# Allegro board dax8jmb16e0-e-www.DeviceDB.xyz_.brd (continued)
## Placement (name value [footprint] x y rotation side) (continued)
PC8101  0.22U/10V_4  [C0402]  13.04 112.78 180 bottom
PC8102  3900p/50V_4  [C0402]  8.14 108.03 270 bottom
PC8103  0.1U/16V_4  [C0402]  6.79 116.54 0 bottom
PC8104  *0.01u/50V_4  [C0402]  10.32 116.54 180 bottom
PC8105  1U/6.3V_4  [C0402]  40.11 79.56 0 top
PC8200  *1u/25V_6  [C0603]  142.27 23.25 270 top
PC8201  0.1U/25V_4  [C0402]  144.79 21.49 0 top
PC8203  0.1U/25V_4  [C0402]  125.61 30.31 0 bottom
PC8204  0.1U/25V_4  [C0402]  123.86 30.31 0 bottom
PC8205  0.1U/25V_4  [C0402]  123.93 31.3 0 bottom
PC8206  2200P/50V_4  [C0402]  116.04 34.09 270 bottom
PC8207  10u/25V_6  [C0603]  115.78 29.7 90 top
PC8208  *10u/25V_6  [C0603]  117.2 30.92 90 top
PC8209  0.1U/25V_4  [C0402]  118.47 30.16 270 top
PC8210  2.2u/16V_6  [C0603]  122.59 22.69 0 top
PC8211  1u/25V_6  [C0603]  123.87 27.06 0 bottom
PC8212  0.047U/25V_4  [C0402]  122.77 25.58 180 bottom
PC8213  *1000p/50V_4  [C0402]  128.61 28.89 270 bottom
PC8214  *68u/25V_7343H2.9  [CC7343-3H]  74.81 32.14 180 bottom
PC8215  0.1U/25V_4  [C0402]  80.55 32.85 270 bottom
PC8216  2200p/50V_4  [C0402]  114.59 27.72 180 top
PC8217  0.1U/25V_4  [C0402]  125.56 18.14 90 bottom
PC8218  0.1U/25V_4  [C0402]  125.61 16.67 180 bottom
PC8219  0.1U/25V_4  [C0402]  126.53 18.14 90 bottom
PC8220  100P/50V_4  [C0402]  130.08 27.41 180 bottom
PC8221  100P/50V_4  [C0402]  131.91 27.79 270 bottom
PC8222  0.1U/16V_4  [C0402]  102.47 33.2 270 bottom
PC8223  *100p/50V_4  [C0402]  134.09 26.17 0 bottom
PC8224  220P/50V_4  [C0402]  131.99 22.33 0 bottom
PC8225  *33u/25V_D6.3H3  [ECAP7X3_5-7_2]  119.21 30.08 90 bottom
PC8226  *10u/25V_6  [C0603]  87.36 32.39 270 bottom
PC8227  10u/25V_6  [C0603]  90.36 32.36 270 bottom
PC8228  10u/25V_6  [C0603]  88.86 32.39 270 bottom
PC8500  3900p/50V_4  [C0402]  156.9 11.64 180 top
PC8501  100p/50V_4  [C0402]  199.37 30.66 270 top
PC8502  0.22u/10V_4  [C0402]  197.26 30.18 270 top
PC8503  *1u/6.3V_4  [C0402]  167.72 11.33 0 top
PC8504  0.1u/25V_4  [C0402]  83.17 28.63 0 top
PC8505  0.1u/25V_4  [C0402]  80.48 30.03 90 bottom
PC8506  2200p/25V_2  [C0201]  82.79 33.2 270 bottom
PC8507  100p/50V_4  [C0402]  90.41 30.03 270 top
PC8508  100p/50V_4  [C0402]  83.8 29.9 180 top
PC8509  *220p/50V_4  [C0402]  171.92 8.87 270 top
PC8600  0.1U/25V_4  [C0402]  180.04 23.14 270 top
PC8601  2.2u/25V_4  [C0402_2]  183.69 21.32 0 bottom
PC8602  2.2u/25V_4  [C0402_2]  181.92 20.71 270 top
PC8603  2.2u/25V_4  [C0402_2]  183.75 22.66 0 bottom
PC8604  *2.2u/25V_4  [C0402_2]  183.69 21.32 0 top
PC8605  0.1U/25V_4  [C0402]  182.23 20.5 270 bottom
PC8606  2200P/50V_4  [C0402]  181.21 20.25 270 bottom
PC8607  *15u/25V_7343H1.2  [CC7343]  184.44 30.59 90 bottom
PC8608  0.1U/25V_4  [C0402]  179.79 25.28 0 bottom
PC8609  *0.1u/6.3V_2  [C0201]  176.23 22.15 270 bottom
PC8610  2200P/50V_4  [C0402]  177.61 22.31 90 top
PC8611  22U/6.3V_6  [C0603]  177.63 32.75 90 top
PC8612  22U/6.3V_6  [C0603]  176.21 32.75 90 top
PC8613  22U/6.3V_6  [C0603]  174.76 32.75 90 top
PC8614  22U/6.3V_6  [C0603]  173.34 32.77 90 top
PC8615  0.1u/6.3V_2  [C0201]  181.21 34.57 0 bottom
PC8616  *150u/6.3V_7343H1.9  [CC7343]  172.65 30.59 270 bottom
PC8617  2.2U/10V_4  [C0402]  177.45 25.3 0 bottom
PC8620  47p/50V_4  [C0402]  175.57 25.35 180 bottom
PC8621  0.1U/25V_4  [C0402]  185.63 23.5 270 top
PC8622  *2.2u/25V_4  [C0402_2]  187.36 20.23 180 bottom
PC8623  *2.2u/25V_4  [C0402_2]  187.25 21.43 180 bottom
PC8624  *2.2u/25V_4  [C0402_2]  187.31 22.28 180 top
PC8625  *2.2u/25V_4  [C0402_2]  187.26 20.74 180 top
PC8626  0.1U/25V_4  [C0402]  187.26 23.69 180 bottom
PC8627  2200P/50V_4  [C0402]  187.26 22.67 180 bottom
PC8628  *15u/25V_7343H1.2  [CC7343]  193.38 27.34 90 top
PC8629  0.1U/25V_4  [C0402]  189.97 18.73 180 bottom
PC8630  *2200p/50V_4  [C0402]  187.31 24.69 0 bottom
PC8631  22U/6.3V_6  [C0603]  194.57 29.75 90 bottom
PC8632  22U/6.3V_6  [C0603]  196.17 33.91 270 bottom
PC8633  22U/6.3V_6  [C0603]  194.65 33.91 270 bottom
PC8634  22U/6.3V_6  [C0603]  195.99 29.75 90 bottom
PC8635  *150u/6.3V_7343H1.9  [CC7343]  201.68 31.04 270 bottom
PC8636  0.1u/6.3V_2  [C0201]  197.34 29.01 90 bottom
PC8637  *0.1u/6.3V_2  [C0201]  194.5 22.67 90 bottom
PC8638  2.2U/10V_4  [C0402]  191.88 19.51 0 bottom
PC8639  10u/6.3V_4  [C0402]  193.58 19.67 270 bottom
PC8641  1000p/25V_4  [C0402]  195.18 20 0 bottom
PC8642  10u/25V_6  [C0603]  188.07 18.29 90 bottom
PC8700  *0.1u/6.3V_2  [C0201]  145.5 13.9 0 bottom
PC8701  *0.1u/6.3V_2  [C0201]  146.24 13.19 0 bottom
PC8702  2200p/25V_2  [C0201]  153.81 25.46 180 bottom
PC8703  0.1u/25V_4  [C0402]  147.13 23.63 90 top
PC8704  0.1u/25V_4  [C0402]  153.41 22.07 180 bottom
PC8705  2.2u/25V_4  [C0402_2]  153.41 23.19 180 bottom
PC8706  *2.2u/25V_4  [C0402_2]  150.97 22.46 90 top
PC8707  *2.2u/25V_4  [C0402_2]  149.78 22.47 90 top
PC8708  2.2u/25V_4  [C0402_2]  153.81 24.47 180 bottom
PC8709  *15u/25V_7343H1.2  [CC7343]  153.25 30.59 90 bottom
PC8710  10u/6.3V_4  [C0402]  149.03 17.79 90 bottom
PC8711  0.1u/25V_4  [C0402]  143.67 19.56 180 bottom
PC8712  0.1u/6.3V_2  [C0201]  149.84 15.04 90 bottom
PC8713  0.033u/16V_4  [C0402]  148.52 15.73 180 bottom
PC8714  *10u/6.3V_4  [C0402]  147.81 19.36 180 bottom
PC8715  1u/6.3V_4  [C0402]  141.08 16.36 180 bottom
PC8716  22u/6.3V_6  [C0603]  142.07 33.84 270 bottom
PC8717  22u/6.3V_6  [C0603]  140.52 27.87 90 bottom
PC8718  *22u/6.3V_6  [C0603]  134.37 29.7 90 bottom
PC8719  *22u/6.3V_6  [C0603]  140.65 33.84 270 bottom
PC8720  *330u/2V_7343H1.9  [CC7343]  137.45 30.59 270 bottom
PC8721  0.1u/6.3V_2  [C0201]  143.21 34.47 90 bottom
PC8722  2200p/25V_2  [C0201]  146.44 22 90 bottom
PC8723  4.7u/6.3V_4  [C0402_2]  162.42 59.57 180 top
PC8724  0.1u/6.3V_2  [C0201]  162.82 60.66 270 top
PC8725  0.22u/6.3V_2  [C0201]  166.91 57.89 180 top
PC8726  22U/6.3V_6  [C0603]  165.74 60.2 90 top
PC8727  *22U/6.3V_6  [C0603]  164.3 60.2 90 top
PC8728  *22p/50V_4  [C0402]  159.98 56.24 270 top
PC8800  4.7u/6.3V_4  [C0402_2]  46.97 98.35 90 top
PC8801  0.1U/16V_4  [C0402]  37.27 93.3 270 top
PC8802  0.1U/16V_4  [C0402]  45.45 93.3 270 top
PC8803  1U/6.3V_4  [C0402]  37.27 95.31 270 top
PC8804  0.01U/50V_4  [C0402]  46.85 103.69 90 top
PC8805  *0.1U/16V_4  [C0402]  47.35 96.65 180 top
PC8806  *0.1U/16V_4  [C0402]  43.26 109.63 90 top
PC8807  *0.1U/16V_4  [C0402]  46.46 95.28 90 top
PC8808  *0.1U/16V_4  [C0402]  36.74 109.2 0 top
PC8809  180p/25V_2  [C0201]  36 98.74 180 top
PC8810  100p/25V_2  [C0201]  36 97.9 180 top
PC8811  22p/25V_2  [C0201]  36 97.06 180 top
PC8812  *0.1U/16V_4  [C0402]  34.48 108.08 270 top
PC8813  *330p/50V_4  [C0402]  46.85 101.91 90 top
PC8814  1U/6.3V_4  [C0402]  46.85 100.13 270 top
PC8815  *680p/50V_4  [C0402]  42.65 105.03 0 top
PC8816  *330p/50V_4  [C0402]  38.59 106.23 180 top
PC8817  330p/50V_4  [C0402]  36.18 103.43 270 top
PC8900  2200P/50V_4  [C0402]  63.92 112.96 0 bottom
PC8901  0.1U/25V_4  [C0402]  63.92 113.98 180 bottom
PC8902  2.2u/25V_4  [C0402_2]  63.86 115.37 180 bottom
PC8903  0.1U/25V_4  [C0402_2]  55.61 119.56 0 top
PC8904  2.2u/25V_4  [C0402_2]  55.61 120.78 0 top
PC8905  2.2u/25V_4  [C0402_2]  65.11 116.88 180 top
PC8906  *15u/25V_7343H1.2  [CC7343]  60.18 123.12 90 bottom
PC8907  0.1U/25V_4  [C0402]  68.81 79.36 0 bottom
PC8908  1U/6.3V_4  [C0402]  54.52 113.8 90 bottom
PC8909  0.1u/25V_4  [C0402]  54.34 107.88 180 bottom
PC8910  330u/2V_7343H1.9  [CC7343]  84.03 120.17 90 bottom
PC8911  *2200p/50V_4  [C0402]  68.44 114.1 90 bottom
PC8912  0.22u/25V_4  [C0402]  51.56 115.34 90 bottom
PC8913  *0.1u/50V_4  [C0402]  51.29 113.98 0 bottom
PC8914  2200P/50V_4  [C0402]  63.02 122.36 90 bottom
PC8915  0.1U/25V_4  [C0402]  65.04 118.98 180 top
PC8916  2.2u/25V_4  [C0402_2]  65.05 120.06 180 top
PC8917  2.2u/25V_4  [C0402_2]  65.05 121.25 180 top
PC8918  2.2u/25V_4  [C0402_2]  65.31 122.36 270 bottom
PC8919  2.2u/25V_4  [C0402_2]  64.11 122.36 270 bottom
PC8920  *15u/25V_7343H1.2  [CC7343]  60.18 112.71 270 bottom
PC8921  1U/6.3V_4  [C0402]  54.42 121.8 90 bottom
PC8922  0.1u/25V_4  [C0402]  54.59 115.63 180 bottom
PC8923  330u/2V_7343H1.9  [CC7343]  88.83 121.54 90 bottom
PC8924  *2200p/50V_4  [C0402]  68.54 117.2 0 top
PC8925  0.22u/25V_4  [C0402]  51.08 121.97 0 bottom
PC8926  *0.1u/50V_4  [C0402]  50.27 120.2 270 bottom
PC8927  *330u/2V_7343H1.9  [CC7343]  93.56 124.95 90 bottom
PC8928  *330u/2V_7343H1.9  [CC7343]  98.28 124.97 90 bottom
PC9000  *2.2u/25V_4  [C0402_2]  57.01 95.18 0 bottom
PC9001  *15u/25V_7343H1.2  [CC7343]  62.84 86.08 180 bottom
PC9002  1U/6.3V_4  [C0402]  54.34 105.47 90 bottom
PC9003  2200P/50V_4  [C0402]  57.01 97.59 180 bottom
PC9004  0.1U/25V_4  [C0402]  57.01 96.45 0 bottom
PC9005  2.2u/25V_4  [C0402_2]  57.03 97.36 0 top
PC9006  2.2u/25V_4  [C0402_2]  57.01 96.17 0 top
PC9007  0.1U/25V_4  [C0402_2]  57.01 94.98 0 top
PC9008  0.1u/25V_4  [C0402]  53.58 98.99 90 bottom
PC9009  330u/2V_7343H1.9  [CC7343]  77.07 101.81 0 bottom
PC9010  *330u/2V_7343H1.9  [CC7343]  79.13 91.67 270 bottom
PC9015  *2200p/50V_4  [C0402]  59.55 107.12 0 bottom
PC9016  0.1u/25V_4  [C0402]  51.96 105.4 0 bottom
PC9017  *0.1u/50V_4  [C0402]  50.56 105.92 90 bottom
PC9018  2200P/50V_4  [C0402]  108.75 119.64 270 bottom
PC9019  0.1U/25V_4  [C0402]  109.89 119.64 90 bottom
PC9020  2.2u/25V_4  [C0402_2]  104.96 119.84 90 top
PC9021  0.1U/25V_4  [C0402_2]  102.78 119.84 90 top
PC9022  2.2u/25V_4  [C0402_2]  106.16 119.84 90 top
PC9023  2.2u/25V_4  [C0402_2]  110.98 119.64 90 bottom
PC9025  1U/6.3V_4  [C0402]  113.65 121.54 0 top
PC9026  0.1u/25V_4  [C0402]  107.7 121.62 270 top
PC9027  22U/6.3V_6  [C0603]  120.12 122.15 180 bottom
PC9028  22U/6.3V_6  [C0603]  120.12 120.73 180 bottom
PC9029  *22U/6.3V_6  [C0603]  120.12 119.31 180 bottom
PC9030  *22U/6.3V_6  [C0603]  116.31 119.51 0 bottom
PC9031  *22U/6.3V_6  [C0603]  116.31 121.09 0 bottom
PC9032  *2200p/50V_4  [C0402]  108.19 129.77 0 bottom
PC9033  0.1u/25V_4  [C0402]  114.02 119.12 0 top
PC9034  *0.1u/50V_4  [C0402]  112.28 117.67 270 top
PC9035  33u/25V_D6.3H3  [ECAP7X3_5-7_2]  62.84 77.73 0 bottom
PC9036  *33u/25V_D6.3H3  [ECAP7X3_5-7_2]  104.4 124.77 270 bottom
PC9200  0.1U/25V_4  [C0402]  121.27 129.22 180 top
PC9201  68P/50V_4  [C0402_2]  132.06 128.58 270 top
PC9202  2.2u/25V_4  [C0402_2]  129.47 128.58 270 top
PC9203  2.2u/25V_4  [C0402_2]  129.55 128.81 270 bottom
PC9204  2.2u/25V_4  [C0402_2]  130.77 128.58 270 top
PC9206  4.7u/6.3V_4  [C0402_2]  130.67 121.47 270 bottom
PC9207  2200P/50V_4  [C0402]  131.96 128.83 90 bottom
PC9208  0.1U/25V_4  [C0402]  130.87 128.81 90 bottom
PC9209  0.1U/25V_4  [C0402]  134.7 123.09 270 bottom
PC9210  *2200p/50V_4  [C0402]  135.49 126.62 180 top
PC9211  22u/6.3V_6  [C0603]  140.52 120.76 180 bottom
PC9212  22u/6.3V_6  [C0603]  140.52 119.33 180 bottom
PC9213  0.1u/6.3V_2  [C0201]  147.4 120.71 0 bottom
PC9214  *0.1U/16V_4  [C0402]  126.91 125.18 90 bottom
PC9216  2200P/50V_4  [C0402]  128.23 121.13 90 bottom
PC9217  1U/6.3V_4  [C0402]  141.46 112.58 90 bottom
PC9218  0.1u/6.3V_2  [C0201]  138.36 109.43 270 bottom
PC9219  *10u/6.3V_4  [C0402_2]  136.93 113.26 270 bottom
PC9220  *10u/6.3V_4  [C0402_2]  136.97 109.53 90 bottom
PC9221  0.1u/6.3V_2  [C0201]  139.1 116.08 180 bottom
PC9222  *0.1u/6.3V_2  [C0201]  139.05 117.28 180 bottom
PC9223  *22u/6.3V_6  [C0603]  144.15 119.16 270 bottom
PC9224  *22u/6.3V_6  [C0603]  142.73 119.16 270 bottom
PC9300  0.1U/25V_4  [C0402]  162.31 22.18 0 top
PC9301  1U/6.3V_4  [C0402]  162.82 24.26 90 bottom
PC9302  2.2u/25V_4  [C0402_2]  159.65 20.43 0 bottom
PC9303  2.2u/25V_4  [C0402_2]  160.03 22.05 0 top
PC9304  2.2u/25V_4  [C0402_2]  159.65 19.21 0 bottom
PC9305  2.2u/25V_4  [C0402_2]  160.03 23.25 0 top
PC9306  2200P/50V_4  [C0402]  160 22.08 180 bottom
PC9307  *15u/25V_7343H1.2  [CC7343]  167.75 30.59 90 bottom
PC9308  0.1U/25V_4  [C0402]  165.64 22.79 90 top
PC9309  0.22u/25V_4  [C0402]  163.69 27.03 0 bottom
PC9310  *0.1U/16V_4  [C0402]  156.42 22.87 0 bottom
PC9311  0.1U/16V_4  [C0402]  163.81 31.53 180 bottom
PC9312  22U/6.3V_6  [C0603]  164.07 32.75 180 bottom
PC9313  22U/6.3V_6  [C0603]  164.07 34.5 180 bottom
PC9314  *2200p/50V_4  [C0402]  158.5 22.99 270 top
PC9315  *22U/6.3V_6  [C0603]  162.95 31.2 180 top
PC9316  *22U/6.3V_6  [C0603]  162.92 29.72 180 top
PC9500  0.1U/16V_4  [C0402]  170.72 31.22 270 top
PC9501  0.1U/16V_4  [C0402]  166.2 31.15 270 top
PC9502  0.1U/16V_4  [C0402]  190.61 32.7 180 top
PC9503  0.1U/16V_4  [C0402]  184.08 32.77 0 top
PC9504  *10u/6.3V_6  [C0603]  165.39 34.37 0 top
PC9505  0.1U/16V_4  [C0402]  165.24 31.93 90 top
PC9506  0.1U/16V_4  [C0402]  170.7 33.23 90 top
PC9507  *10u/6.3V_6  [C0603]  190.15 30.51 270 top
PC9508  *10u/6.3V_6  [C0603]  171.92 32.77 90 top
PC9509  0.1U/16V_4  [C0402]  188.85 28.05 90 top
PC9510  0.1U/16V_4  [C0402]  185.45 30.92 270 top
PC9511  *10u/6.3V_6  [C0603]  184.16 30.76 270 top
PC9512  0.1U/16V_4  [C0402]  188.04 34.96 270 top
PC9513  0.1U/16V_4  [C0402]  167.98 28.71 90 top
PC9514  *0.1U/16V_4  [C0402]  184.92 35.46 180 top
PC9515  1N/50V_4  [C0402]  187.87 28.1 90 top
PC9516  1N/50V_4  [C0402]  186.65 28.07 90 top
PC9517  *0.1U/16V_4  [C0402]  168.94 28.73 90 top
PC9518  1N/50V_4  [C0402]  168 34.6 270 top
PC9519  1N/50V_4  [C0402]  169.02 34.6 270 top
PC9520  *0.1U/16V_4  [C0402]  166.99 29.01 90 top
PC9521  *0.1U/16V_4  [C0402]  189.03 34.45 270 top
PC9522  0.1U/16V_4  [C0402]  152.36 30.41 270 top
PC9523  0.1U/16V_4  [C0402]  156.78 30.16 270 top
PC9524  *0.1U/16V_4  [C0402]  184.56 34.12 90 top
PC9525  *0.1U/16V_4  [C0402]  181.92 32.39 90 top
PC9526  *10u/6.3V_6  [C0603]  150.15 31.17 90 top
PC9527  0.1U/16V_4  [C0402]  151.37 30.97 90 top
PC9528  0.1U/16V_4  [C0402]  157.74 31.3 90 top
PC9529  *10u/6.3V_6  [C0603]  157.82 32.9 180 top
PC9530  *0.1U/16V_4  [C0402]  171.9 28.9 90 top
PC9531  0.1U/16V_4  [C0402]  154.64 28.38 90 top
PC9532  *0.1U/16V_4  [C0402]  155.61 28.38 90 top
PC9533  1N/50V_4  [C0402]  154.03 34.04 270 top
PC9534  1N/50V_4  [C0402]  155.08 34.04 270 top
PC9535  *0.1U/16V_4  [C0402]  153.68 28.38 90 top
PC9600  0.1U/16V_4  [C0402]  134.6 107.29 180 top
PC9601  0.1U/16V_4  [C0402]  135.19 111.54 0 top
PC9602  *10u/6.3V_6  [C0603]  136.81 113.52 270 top
PC9603  0.1U/16V_4  [C0402]  132.77 106.46 0 top
PC9604  0.1U/16V_4  [C0402]  130.51 108.79 90 top
PC9605  *10u/6.3V_6  [C0603]  129.85 110.55 0 top
PC9606  0.1U/16V_4  [C0402]  118.47 61.8 270 top
PC9607  0.1U/16V_4  [C0402]  125.08 62.72 180 top
PC9608  *10u/6.3V_6  [C0603]  124.67 61.5 180 top
PCN8000  CONN SMD HEADER 8P 1R MR  [51483-00801-V01-8P-L]  221.02 113.16 0 bottom
PCN8500  CONN DIP BATT 8P 1R MR  [BAT-BBP28EC-B301Q-9H-8P-L-SMT]  90.2 26.59 180 bottom
PD8000  P4SMAFJ20A  [D-3_8X2_5]  217.87 107.22 0 top
PD8001  PDZ5.1B  [DSM]  194.34 85.48 180 top
PD8100  BAT54AW-L  [SOT323_213-2_1-1_3-3P]  15.43 110.01 0 bottom
PD8101  *PDZ5.6B  [DSM]  89.52 32.97 180 top
PD8200  *P4SMAFJ20A  [D-3_8X2_5]  131.28 33.53 0 bottom
PD8201  PDZ5.1B  [DSM]  98.94 32.44 0 top
PD8202  BAS316  [D-SOD323-1_7X1_25-PMEG4005AEA]  125.1 28.66 0 top
PD8203  *UDZ8V2B-7  [DSM]  125.99 22.18 0 top
PD8204  BAS316  [D-SOD323-1_7X1_25-PMEG4005AEA]  119.64 24.95 180 top
PD8205  SX34  [D-4_3X2_7]  74.81 28.07 180 bottom
PD8206  BAS316  [D-SOD323-1_7X1_25-PMEG4005AEA]  129.42 30.89 0 bottom
PD8207  BAT54CW  [UMT_213-3-1_3]  188.76 96.09 0 top
PD8500  BAV99-7-F  [SOT23_213-3_3-2]  86.6 31.17 270 top
PD8501  BAV99-7-F  [SOT23_213-3_3-2]  81.01 31.3 270 top
PD8700  RB500V-40  [DSM]  171.13 58.76 180 top
PL8000  *Short_0805  [S0805]  215.34 104.43 90 bottom
PL8001  *Short_0805  [S0805]  217.88 104.81 90 bottom
PL8200  HCB1608KF-121T30  [R0603]  125.71 33.84 90 bottom
PL8201  HCB1608KF-121T30  [R0603]  124.06 33.84 90 bottom
PL8202  2.2uH_7x7x3_dcr20  [CHOKE-PCMC063T-3R3MN-SMT]  106.92 29.77 180 bottom
PL8500  *Short_0805  [S0805]  82.05 30.78 270 bottom
PL8501  *Short_0805  [S0805]  84.21 30.78 270 bottom
PL8600  1uH_7x7x3  [CHOKE-PCMC063T-3R3MN-SMT]  178.52 30.31 90 bottom
PL8601  1.5uH_7x7x3  [CHOKE-PCMC063T-3R3MN-SMT]  190.46 30.74 90 bottom
PL8700  HCB1608KF-121T30  [R0603]  148.4 23.98 270 top
PL8701  1uH_7x7x3  [CHOKE-PCMC063T-3R3MN-SMT]  146.39 29.65 180 bottom
PL8702  2.2uH_2.5x2.0x1.2  [L2_5X2-1_2H]  167.86 59.86 90 top
PL8900  HCB1608KF-121T30  [R0603]  71.61 84.64 315 bottom
PL8901  HCB1608KF-121T30  [R0603]  70.59 83.62 315 bottom
PL8902  0.24uH_10x10x3  [CHOKE-ETQP4L]  75.67 109.35 0 bottom
PL8903  0.24uH_10x10x3  [CHOKE-ETQP4L]  75.67 119.72 0 bottom
PL9000  0.15uH_7x7x3  [CHOKE-PCMC063T-3R3MN-SMT]  66.01 103.05 0 bottom
PL9001  0.47uH_7x7x3  [CHOKE-PCMC063T-3R3MN-SMT]  117.15 126.27 0 bottom
PL9200  HCB1608KF-121T30  [R0603]  121.27 127.95 0 top
PL9201  2.2uH_7x7x3  [CHOKE-PCMC063T-3R3MN-SMT]  139.43 126.04 0 bottom
PL9300  1uH_7x7x3  [L6_6X6_6-2_8H]  159.19 30.69 90 bottom
PQ8000  EMB03P03H  [POWER-5_2X5_55-1_27-5P]  216.98 101.78 90 top
PQ8001  AONR21357  [DFN-8L-3X3-65-5P-0_9H]  222.72 101 90 top
PQ8002  BSS84  [SOT23_213-3_3-2]  201.02 96.88 0 top
PQ8003  BSS84  [SOT23_213-3_3-2]  204.63 93.07 180 top
PQ8004  PJA138K  [SOT23_213-3_3-2]  206.76 96.73 180 top
PQ8005  2N7002KDW  [SOT363-2_1-65-6P]  201.3 93.76 0 top
PQ8006  AONR21357  [POWER-3_1X3_1-65-5P]  217.66 96.65 180 top
PQ8007  AONR21357  [POWER-3_1X3_1-65-5P]  212.76 96.93 0 top
PQ8008  BSS84  [SOT23_213-3_3-2]  198.46 85.45 270 top
PQ8009  BSS84  [SOT23_213-3_3-2]  198 89.31 270 top
PQ8010  METR3906-G  [SOT23_213-3_3-2]  197.72 94.06 270 top
PQ8011  METR3906-G  [SOT23_213-3_3-2]  193.96 88.37 270 top
PQ8012  MMDT2907A-7-F  [SOT363-2_1-65-6P]  202.88 85.17 0 top
PQ8013  MMDT2907A-7-F  [SOT363-2_1-65-6P]  202.88 87.71 0 top
PQ8100  *2N7002KDW  [SOT363-2_1-65-6P]  35.8 81.59 270 top
PQ8200  AONS21357  [POWER-5_2X5_55-1_27-5P]  110.7 33.13 0 top
PQ8201  BSS84  [SOT23_213-3_3-2]  104.5 31.22 180 top
PQ8202  MMDT2907A-7-F  [SOT363-2_1-65-6P]  103.64 34.32 180 top
PQ8203  AON7408  [DFN-8L-3X3-65-5P-0_9H]  113.52 31.48 270 bottom
PQ8204  AON7408  [DFN-8L-3X3-65-5P-0_9H]  113.5 27.59 0 bottom
PQ8206  2N7002K  [SOT23_213-3_3-2]  135.09 18.12 0 bottom
PQ8500  PMBT3906  [SOT23_213-3_3-2]  158.48 12.96 90 top
PQ8501  PMST3904  [UMT_213-3-1_3]  153.37 9.25 0 top
PQ8502  2N7002K  [SOT23_213-3_3-2]  152.51 12.6 0 top
PQ8503  2N7002K  [SOT23_213-3_3-2]  135.29 21.82 270 bottom
PQ8505  *PMBT3906  [SOT23_213-3_3-2]  169.35 8.95 270 top
PQ8506  *PMBT3906  [SOT23_213-3_3-2]  165.62 8.95 270 top
PQ8700  AON7408  [DFN-8L-3X3-65-5P-0_9H]  149.84 24.11 180 bottom
PQ8701  AON7752  [DFN-8L-3X3-65-5P-0_9H]  143.87 23.81 270 bottom
PQ8702  *2N7002K  [SOT23_213-3_3-2]  163.03 10.65 90 top
PQ8703  2N7002KDW  [SOT363-2_1-65-6P]  152.76 18.75 270 bottom
PQ8900  AOE6932  [POWER-5X6-1_27-10P]  66.4 109.66 90 bottom
PQ8901  AOE6932  [POWER-5X6-1_27-10P]  66.4 118.67 90 bottom
PQ9000  AON6992  [POWER-5X6-1_27-7P-0_8H]  58.78 103.08 180 bottom
PQ9001  AON7408  [PG-TSDSON-8-8P-R]  110.04 122.97 90 bottom
PQ9002  AON7752  [PG-TSDSON-8-8P-R]  110.39 127.15 180 bottom
PQ9600  EMF11N02J  [SOT23_213-3_3-2]  137.78 110.06 90 top
PQ9601  *2N7002KDW  [SOT363-2_1-65-6P]  179.66 112.17 0 top
PQ9602  EMF11N02J  [SOT23_213-3_3-2]  132.9 108.92 90 top
PQ9603  2N7002KDW  [SOT363-2_1-65-6P]  175.55 111.99 0 top
PQ9604  EMF11N02J  [SOT23_213-3_3-2]  119.79 60.05 0 top
PQ9605  *2N7002KDW  [SOT363-2_1-65-6P]  125.2 59.47 0 top
PR8000  220K_5%_4  [R0402]  204.94 100.39 0 top
PR8001  20K_1%_4  [R0402]  204.35 97.82 90 top
PR8002  1K_1%_6  [R0603]  225.53 106.05 0 bottom
PR8003  20K_1%_4  [R0402]  206.56 91.39 180 top
PR8004  1K_1%_6  [R0603]  228.18 106.05 180 bottom
PR8005  200K_1%_4  [R0402]  208.87 95.51 180 top
PR8006  10K_1%_4  [R0402]  203.77 96.45 0 top
PR8007  200K_1%_4  [R0402]  200.36 90.66 0 top
PR8008  10K_1%_4  [R0402]  203.74 95.48 0 top
PR8009  100K_1%_4  [R0402]  214.02 105.78 270 top
PR8010  10K_1%_4  [R0402]  220.3 101.88 270 top
PR8011  100K_1%_4  [R0402]  206.36 94.39 0 top
PR8012  300K_1%_4  [R0402]  200.31 91.9 180 top
PR8013  100K_1%_4  [R0402]  202.27 91.65 90 top
PR8014  549K_1%_4  [R0402]  199.3 95.41 0 top
PR8015  76.8K_1%_4  [R0402]  196.4 91.24 90 top
PR8016  47K_1%_4  [R0402]  205.24 85.55 180 top
PR8017  47K_1%_4  [R0402]  205.24 88.4 180 top
PR8018  470K_5%_4  [R0402]  196.55 86.97 0 top
PR8019  220K_5%_4  [R0402]  191.6 86.16 90 top
PR8020  1M_5%_4  [R0402]  191.63 89.97 270 top
PR8021  33K_1%_4  [R0402]  195.28 90.1 90 top
PR8022  100K_1%_4  [R0402]  191.6 88.17 90 top
PR8023  100K_1%_4  [R0402]  200.85 84.18 90 top
PR8024  100K_1%_4  [R0402]  200.44 87.38 270 top
PR8025  470K_5%_4  [R0402]  205.24 84.41 180 top
PR8026  470K_5%_4  [R0402]  205.24 87.43 180 top
PR8100  10K_1%_4  [R0402]  14.28 116.01 0 bottom
PR8101  115K_1%_4  [R0402]  14.33 111.77 180 bottom
PR8102  76.8K_1%_4  [R0402]  14.28 114.81 180 bottom
PR8103  51.1K_1%_4  [R0402]  163.46 19.92 0 bottom
PR8104  41.2K_1%_4  [R0402]  14.79 112.78 180 bottom
PR8105  28K_1%_4  [R0402]  161.76 20.02 270 bottom
PR8106  *3.3K_1%_4  [R0402]  14.28 113.8 180 bottom
PR8107  57.6K_1%_4  [R0402]  4.53 110.37 0 bottom
PR8108  3.3K_1%_4  [R0402]  163.56 21.27 270 bottom
PR8109  31.6K_1%_4  [R0402]  3.36 111.79 270 bottom
PR8110  3.3K_1%_4  [R0402]  9.13 108.03 270 bottom
PR8111  10K_1%_4  [R0402]  12.53 113.8 0 bottom
PR8112  10K_1%_4  [R0402]  6.61 109.83 90 bottom
PR8113  1K_1%_4  [R0402]  17.76 110.55 180 bottom
PR8114  3.3K_1%_4  [R0402]  17.76 109.53 180 bottom
PR8115  18.7K_1%_4  [R0402]  12.53 111.77 0 bottom
PR8116  22.6K_1%_4  [R0402]  7.17 108.03 90 bottom
PR8117  1M_5%_4  [R0402]  12.53 114.81 0 bottom
PR8118  1M_5%_4  [R0402]  7.63 109.83 270 bottom
PR8119  20K_1%_4  [R0402]  12.53 116.01 180 bottom
PR8120  20K_1%_4  [R0402]  8.64 109.83 270 bottom
PR8121  100K_1%_4  [R0402]  41.89 79.56 180 top
PR8122  10K_1%_4  [R0402]  42.91 78.54 0 top
PR8123  100_1%_4  [R0402]  41.13 78.54 0 top
PR8125  *100K_5%_4  [R0402]  37.57 81.59 90 top
PR8126  *100K_5%_4  [R0402]  36.3 83.75 0 top
PR8127  *0_5%_4  [R0402]  38.72 79.18 90 top
PR8129  *100K_5%_4  [R0402]  89.77 34.47 180 top
PR8130  *10K_5%_4  [R0402]  92.57 31.17 0 top
PR8200  0.01_1%_12  [R1206]  140.01 23.35 270 top
PR8201  *Short_0201  [S0201]  140.01 22.59 270 top
PR8202  *Short_0201  [S0201]  140.01 24.11 90 top
PR8203  47K_1%_4  [R0402]  100.49 34.57 180 top
PR8204  470K_5%_4  [R0402]  101.58 32.82 270 top
PR8205  100_1%_4  [R0402]  125.54 28.86 90 bottom
PR8206  100_1%_4  [R0402]  124.52 28.86 90 bottom
PR8207  100K_1%_4  [R0402]  114.97 34.96 180 top
PR8208  470K_5%_4  [R0402]  98.74 34.57 0 top
PR8209  4.02K_1%_4  [R0402]  126.6 28.94 90 bottom
PR8210  10_5%_8  [R0805]  122.92 25.1 270 top
PR8211  *0_5%_4/S  [S0402]  123.5 28.86 90 bottom
PR8212  0_5%_6  [R0603]  122.21 24.39 180 bottom
PR8213  249K_1%_4  [R0402]  130.64 28.89 90 bottom
PR8214  0.005_1%_12  [R1206]  99.3 30.71 0 bottom
PR8215  40.2K_1%_4  [R0402]  129.62 28.89 270 bottom
PR8216  2.2_5%_6  [R0603]  112.38 27.82 0 top
PR8217  *Short_0201  [S0201]  100.06 30.71 0 bottom
PR8218  *Short_0201  [S0201]  98.53 30.71 180 bottom
PR8219  *0_5%_4/S  [S0402]  131.73 24.29 180 bottom
PR8220  *0_5%_4/S  [S0402]  131.73 23.32 180 bottom
PR8221  *0_5%_4/S  [S0402]  131.71 25.25 0 bottom
PR8222  *0_5%_4  [R0402]  130.67 19.84 270 bottom
PR8223  10_1%_6  [R0603]  128.48 20.35 90 bottom
PR8224  *0_5%_4/S  [S0402]  130.41 21.75 270 bottom
PR8225  *0_5%_6/S  [S0603]  125.64 20.35 90 bottom
PR8226  22K_1%_4  [R0402]  128.63 27.21 90 top
PR8227  *0_5%_6/S  [S0603]  127.06 20.35 90 bottom
PR8228  2M_1%_4  [R0402]  127.59 28.89 270 bottom
PR8229  *0_5%_4/S  [S0402]  131.99 29.14 0 bottom
PR8230  *0_5%_4/S  [S0402]  133.41 27.51 90 bottom
PR8233  47K_1%_4  [R0402]  124.32 22.38 0 bottom
PR8235  *0_5%_4  [R0402]  134.4 27.51 90 bottom
PR8236  10K/F_4  [R0402]  102.85 34.73 0 bottom
PR8237  *0_5%_4  [R0402]  131.68 26.22 180 bottom
PR8238  47K_1%_4  [R0402]  131.66 20 90 bottom
PR8240  249K_1%_4  [R0402]  133.82 24.24 0 bottom
PR8241  1M_1%_4  [R0402]  131.99 21.34 0 bottom
PR8242  *0_5%_4/S  [S0402]  132.62 20 90 bottom
PR8243  28K_1%_4  [R0402]  135.54 24.16 180 bottom
PR8244  402_1%_4  [R0402]  136.89 23.6 90 bottom
PR8245  *0_5%_4/S  [S0402]  191.32 96.04 180 top
PR8246  *0_5%_4/S  [S0402]  191.32 97.01 180 top
PR8247  47K_5%_4  [R0402]  132.44 30.33 0 bottom
PR8248  27K_1%_4  [R0402]  133.74 31.5 0 bottom
PR8500  49.9K_1%_4  [R0402]  199.37 32.19 0 top
PR8501  100K_1%_4  [R0402]  155.94 9.48 180 top
PR8502  301K_1%_4  [R0402]  198.25 30.18 90 top
PR8503  9.09K_1%_4  [R0402]  158.61 10.24 90 top
PR8504  3.32K_1%_4  [R0402]  160.16 10.24 0 top
PR8505  1.87K_1%_4  [R0402]  157.62 10.24 90 top
PR8506  1.87K_1%_4  [R0402]  155.94 10.44 180 top
PR8507  49.9K_1%_4  [R0402]  196.27 30.18 90 top
PR8508  9.09K_1%_4  [R0402]  160.16 11.21 0 top
PR8509  100K_1%_4  [R0402]  154.85 12.65 90 top
PR8511  *549K_1%_4  [R0402]  172.55 13.72 270 top
PR8512  100K_1%_4  [R0402]  92.06 29.52 0 top
PR8513  *76.8K_1%_4  [R0402]  172.32 10.62 90 top
PR8514  *220K_1%_4  [R0402]  167.72 10.37 0 top
PR8515  *0_5%_4/S  [S0402]  93.96 29.52 0 top
PR8516  100_1%_4  [R0402]  89.39 31.43 0 top
PR8517  100_1%_4  [R0402]  83.8 31.04 0 top
PR8518  *100K_1%_4  [R0402]  165.74 11.71 90 top
PR8519  *0_5%_4/S  [S0402]  135.72 25.13 180 bottom
PR8520  *0_5%_4/S  [S0402]  133.71 25.2 180 bottom
PR8600  HCB1608KF-121T30  [R0603]  181.24 22.89 270 top
PR8601  0_5%_6  [R0603]  181.36 25.35 270 bottom
PR8602  2.05K_1%_4  [R0402]  175.32 23.42 180 bottom
PR8603  *0_5%_4/S  [S0402]  178.54 19.49 270 bottom
PR8604  100K_1%_4  [R0402]  175.37 22.05 90 bottom
PR8605  2.2_5%_6  [R0603]  178.06 23.88 180 top
PR8606  *Short_0201  [S0201]  175.01 32.97 90 top
PR8608  0_5%_4  [R0402]  175.57 24.39 0 bottom
PR8609  150K_1%_4  [R0402]  176.56 20.27 90 bottom
PR8610  499K_1%_4  [R0402]  175.6 20.33 90 bottom
PR8611  HCB1608KF-121T30  [R0603]  187.69 25.05 0 top
PR8615  *2.2_5%_6  [R0603]  189.72 25.46 180 bottom
PR8616  100K_1%_4  [R0402]  195.81 21.94 180 bottom
PR8617  *Short_0201  [S0201]  197.62 29.32 0 bottom
PR8619  1K_1%_4  [R0402]  195.19 20.97 180 bottom
PR8622  *0_5%_6/S  [S0603]  179.05 33.43 270 top
PR8623  *0_5%_6/S  [S0603]  205.37 36.07 0 bottom
PR8624  *0_5%_6/S  [S0603]  205.37 34.65 0 bottom
PR8625  *150K_1%_4  [R0402]  195.56 24.95 270 bottom
PR8626  100K_1%_4  [R0402]  194.42 24.95 90 bottom
PR8627  *0_5%_4/S  [S0402]  189.85 19.61 180 top
PR8628  100K_1%_4  [R0402]  195.81 22.95 0 bottom
PR8630  HCB1608KF-121T30  [R0603]  187.69 26.47 0 top
PR8700  *0_5%_4/S  [S0402]  143.49 13.39 270 bottom
PR8701  *0_5%_4/S  [S0402]  146.13 11.77 0 bottom
PR8702  324K_1%_4  [R0402]  141.41 17.71 90 bottom
PR8703  *0_5%_4/S  [S0402]  147.61 12.76 0 bottom
PR8704  499K_1%_4  [R0402]  144.48 13.39 90 bottom
PR8705  2.2_5%_6  [R0603]  144.28 21.14 180 bottom
PR8706  100_5%_4  [R0402]  148.52 14.71 0 bottom
PR8707  2.2_5%_6  [R0603]  146.49 23.81 270 bottom
PR8708  *Short_0603  [S0603]  147.25 20.12 90 bottom
PR8709  *Short_0201  [S0201]  148.04 16.62 0 bottom
PR8710  *Short_0201  [S0201]  141.36 28.43 180 bottom
PR8711  *Short_0201  [S0201]  142.32 15.45 270 bottom
PR8712  *0_5%_4  [R0402]  163.03 7.85 90 top
PR8713  7.87K_1%_4  [R0402]  147.61 13.75 180 bottom
PR8714  10K_1%_4  [R0402]  149.49 12.98 180 bottom
PR8715  *Short_0603  [S0603]  160.1 60.13 180 top
PR8716  *0_5%_4/S  [S0402]  160.21 58.93 180 top
PR8717  *0_5%_6/S  [S0603]  166.15 62.28 180 top
PR8718  200K_1%_4  [R0402]  154.49 18.14 270 bottom
PR8719  100_1%_4  [R0402]  167.24 56.09 180 top
PR8720  22_5%_8  [R0805]  150.53 18.83 90 bottom
PR8721  100K_1%_4  [R0402]  167.24 57.05 0 top
PR8722  *Short_0201  [S0201]  161.96 60.94 0 top
PR8723  32.4K_1%_4  [R0402]  160.99 56.24 270 top
PR8724  10K_1%_4  [R0402]  160.46 57.97 180 top
PR8725  *0_5%_6/S  [S0603]  144.89 33.97 0 bottom
PR8800  4.7_5%_4  [R0402]  48.12 98.35 90 top
PR8801  100_1%_4  [R0402]  39.35 93.3 270 top
PR8802  *75_1%_4  [R0402]  40.37 93.3 270 top
PR8803  45.3_1%_4  [R0402]  38.34 93.3 270 top
PR8804  *75_1%_4  [R0402]  42.4 93.3 270 top
PR8805  4.7K_1%_4  [R0402]  44.46 93.3 270 top
PR8806  4.7K_1%_4  [R0402]  43.42 93.3 270 top
PR8807  2M_1%_4  [R0402]  48.88 103.69 90 top
PR8808  133K_1%_4  [R0402]  47.86 103.69 90 top
PR8809  *0_5%_4/S  [S0402]  44.46 95.31 270 top
PR8810  75_1%_4  [R0402]  42.4 95.31 270 top
PR8811  *0_5%_4/S  [S0402]  47.48 95.28 90 top
PR8812  *0_5%_2/S  [S0201]  45.3 95.99 270 top
PR8813  1.5K_1%_4  [R0402]  44.05 105.59 270 top
PR8814  1.5K_1%_4  [R0402]  45.07 105.59 90 top
PR8815  *0_5%_4/S  [S0402]  43.42 95.31 270 top
PR8816  *10K_1%_4  [R0402]  41.38 93.3 270 top
PR8817  1.5K_1%_4  [R0402]  46.08 105.59 90 top
PR8818  *0_5%_2/S  [S0201]  41.38 95.56 270 top
PR8819  1.5K_1%_4  [R0402]  47.1 105.59 90 top
PR8820  *0_5%_4/S  [S0402]  40.37 95.31 90 top
PR8821  10_1%_4  [R0402]  39.35 95.31 270 top
PR8822  1.33K_1%_4  [R0402]  42.65 106 0 top
PR8823  49.9_1%_4  [R0402]  38.34 95.31 270 top
PR8824  *0_5%_4  [R0402]  42.27 109.63 270 top
PR8825  *10K_5%_4  [R0402]  46.46 93.3 270 top
PR8826  *100_1%_4  [R0402]  112.3 111.82 0 bottom
PR8827  *0_5%_4/S  [S0402]  48.5 93.3 270 top
PR8828  *0_5%_4/S  [S0402]  41.05 105.59 270 top
PR8829  *0_5%_4/S  [S0402]  40.06 105.59 270 top
PR8830  100K_5%_4  [R0402]  47.48 93.3 90 top
PR8831  61.9K_1%_4  [R0402]  35.87 95.81 180 top
PR8832  2.43K_1%_4  [R0402]  38.59 105.21 0 top
PR8833  *100_1%_4  [R0402]  114.03 111.94 270 bottom
PR8834  *0_5%_4  [R0402]  38.59 109.2 0 top
PR8835  100_1%_4  [R0402]  37.07 107.75 270 top
PR8836  47K_1%_4  [R0402]  34.02 98.86 0 top
PR8837  *0_5%_4/S  [S0402]  37.07 105.59 270 top
PR8838  121K_1%_4  [R0402]  34.02 97.85 180 top
PR8839  *0_5%_4/S  [S0402]  36.05 105.59 270 top
PR8840  619K_1%_4  [R0402]  34.02 96.83 180 top
PR8841  100_1%_4  [R0402]  36.05 107.75 270 top
PR8842  100/F_4  [R0402]  33.94 101.91 0 top
PR8843  *0_5%_4/S  [S0402]  35.92 101.91 0 top
PR8844  *0_5%_4/S  [S0402]  35.92 100.89 0 top
PR8845  100/F_4  [R0402]  33.94 100.89 0 top
PR8846  *0_5%_2  [R0201]  49.26 102.29 0 top
PR8847  *0_5%_2/S  [S0201]  49.26 101.53 180 top
PR8848  8.2K_1%_4  [R0402]  35.16 103.43 90 top
PR8849  *0_5%_4  [R0402]  34.48 106.3 270 top
PR8850  *9.1K_1%_4  [R0402]  47.96 101.91 90 top
PR8851  49.9K_1%_4  [R0402]  47.96 100.13 90 top
PR8852  *0_5%_4  [R0402]  44.05 107.75 90 top
PR8853  *0_5%_4  [R0402]  47.1 107.75 90 top
PR8854  *0_5%_4  [R0402]  33.94 99.88 180 top
PR8855  *0_5%_4  [R0402]  45.07 107.75 270 top
PR8856  102K_1%_4  [R0402]  46.08 107.75 270 top
PR8857  *510K_1%_4  [R0402]  35.92 99.88 0 top
PR8858  *0_5%_4  [R0402]  42.4 108.26 0 top
PR8859  154K_1%_4  [R0402]  42.4 107.24 0 top
PR8860  *0_5%_4  [R0402]  38.59 108.21 0 top
PR8861  523K_1%_4  [R0402]  38.59 107.24 0 top
PR8862  909_1%_4  [R0402]  32.27 98.86 0 top
PR8863  0_5%_4  [R0402]  32.27 97.85 180 top
PR8864  0_5%_4  [R0402]  32.27 96.83 180 top
PR8865  *0_5%_4  [R0402]  48.98 100.13 90 top
PR8866  1M_1%_4  [R0402]  34.02 103.43 90 top
PR8867  *0_5%_4  [R0402]  34 104.92 180 top
PR8900  1_5%_6  [R0603]  56.12 108.9 90 bottom
PR8901  *0_5%_2/S  [S0201]  50.99 110.14 0 bottom
PR8902  *Short_0201  [S0201]  73.13 109.35 180 bottom
PR8903  *0_5%_2/S  [S0201]  50.99 111.66 0 bottom
PR8904  *2.2_5%_6  [R0603]  69.71 113.98 270 bottom
PR8905  *Short_0201  [S0201]  78.09 109.35 0 bottom
PR8906  *0_5%_2/S  [S0201]  52.69 107.75 90 bottom
PR8907  *0_5%_2/S  [S0201]  50.53 110.93 0 bottom
PR8908  1.62K_1%_4  [R0402]  74.66 109.91 180 top
PR8909  10K_NTC_4_1%  [R0402]  81.45 112.67 90 bottom
PR8910  1.74K_1%_4  [R0402]  77.07 108.39 90 top
PR8911  348_1%_4  [R0402]  53.37 113.8 270 bottom
PR8912  374_1%_4  [R0402]  76.44 109.91 180 top
PR8913  12K_1%_4  [R0402]  76.06 108.39 90 top
PR8914  348_1%_4  [R0402]  51.29 112.96 0 bottom
PR8915  1_5%_6  [R0603]  56.24 116.64 90 bottom
PR8916  *0_5%_2/S  [S0201]  51.29 117.4 0 bottom
PR8917  *2.2_5%_6  [R0603]  70.77 117.28 0 top
PR8918  *Short_0201  [S0201]  73.26 119.64 180 bottom
PR8919  *Short_0201  [S0201]  78.19 119.61 0 bottom
PR8920  *0_5%_2/S  [S0201]  51.29 118.93 0 bottom
PR8921  *0_5%_2/S  [S0201]  53.32 115.63 90 bottom
PR8922  *0_5%_2/S  [S0201]  51.29 118.17 0 bottom
PR8923  1.62K_1%_4  [R0402]  73.44 115.42 270 top
PR8924  10K_NTC_4_1%  [R0402]  80.01 125.38 180 bottom
PR8925  1.74K_1%_4  [R0402]  76.49 114.41 90 top
PR8926  348_1%_4  [R0402]  53.15 121.8 270 bottom
PR8927  374_1%_4  [R0402]  74.84 115.8 180 top
PR8928  12K_1%_4  [R0402]  75.47 114.41 90 top
PR8929  348_1%_4  [R0402]  51.29 120.2 270 bottom
PR9000  *0_5%_2/S  [S0201]  51.39 101.12 0 bottom
PR9001  1_5%_6  [R0603]  55.23 99.12 90 bottom
PR9002  *0_5%_2/S  [S0201]  51.39 102.64 0 bottom
PR9003  *0_5%_2/S  [S0201]  52.69 98.99 90 bottom
PR9004  *2.2_5%_6  [R0603]  61.83 107.24 0 bottom
PR9005  *Short_0201  [S0201]  63.8 102.97 180 bottom
PR9006  *Short_0201  [S0201]  68.19 103 0 bottom
PR9007  *0_5%_2/S  [S0201]  51.39 101.88 0 bottom
PR9008  3K_1%_4  [R0402]  63.86 98.61 90 bottom
PR9009  10K_NTC_4_1%  [R0402]  68.39 98.66 0 bottom
PR9010  316_1%_4  [R0402]  66.91 98.61 270 bottom
PR9011  237_1%_4  [R0402]  53.32 105.47 270 bottom
PR9012  309_1%_4  [R0402]  65.26 97.08 180 bottom
PR9013  10K_1%_4  [R0402]  65.9 98.61 270 bottom
PR9014  237_1%_4  [R0402]  51.39 104.04 270 bottom
PR9015  1_5%_6  [R0603]  109.1 124.01 270 top
PR9016  *0_5%_2/S  [S0201]  107.21 118.25 90 top
PR9017  *0_5%_2/S  [S0201]  109.53 118.04 90 top
PR9018  *0_5%_2/S  [S0201]  107.16 120.07 90 top
PR9019  *2.2_5%_6  [R0603]  110.47 129.72 0 bottom
PR9020  *Short_0201  [S0201]  114.99 126.27 180 bottom
PR9021  *Short_0201  [S0201]  119.31 126.27 0 bottom
PR9022  *0_5%_2/S  [S0201]  107.98 118.25 90 top
PR9023  1.96K_1%_4  [R0402]  112.89 125.15 0 top
PR9024  10K_NTC_4_1%  [R0402]  116.57 122.36 180 bottom
PR9025  2.32K_1%_4  [R0402]  115.27 124.62 270 top
PR9026  1.15K_1%_4  [R0402]  113.9 120.3 180 top
PR9027  215_1%_4  [R0402]  114.72 123.25 180 top
PR9028  10K_1%_4  [R0402]  114.26 124.62 270 top
PR9029  1.15K_1%_4  [R0402]  111.26 117.67 90 top
PR9200  95.3K_1%_4  [R0402]  128.11 127.63 90 bottom
PR9201  5.1_5%_6  [R0603]  133.07 120.23 0 bottom
PR9202  1_5%_6  [R0603]  132.57 122.23 0 bottom
PR9203  *0_4/S  [S0402]  128.73 123 90 bottom
PR9204  *2.2_5%_6  [R0603]  137.75 126.98 180 top
PR9205  *0_2/S  [S0201]  128.81 125.3 90 bottom
PR9206  *0_2/S  [S0201]  141.16 121.37 270 bottom
PR9207  *0_5%_4/S  [S0402]  127.24 123.63 180 bottom
PR9208  *470K_4  [R0402]  127.92 125.18 270 bottom
PR9209  3.16K_1%_4  [R0402]  126.18 127.63 270 bottom
PR9210  10K_1%_4  [R0402]  127.15 127.63 270 bottom
PR9211  *0_5%_4/S  [S0402]  140.5 116.01 180 bottom
PR9212  *Short_0603  [S0603]  134.58 112.78 90 bottom
PR9213  *Short_1206  [S1206]  147.33 119 0 bottom
PR9214  10K_1%_4  [R0402]  147.43 116.62 90 bottom
PR9215  *0_5%_4  [R0402]  140.53 117.69 0 bottom
PR9216  0_5%_4  [R0402]  146.44 116.62 270 bottom
PR9217  *0_5%_4  [R0402]  147.43 115.12 0 bottom
PR9300  *0_4/S  [S0402]  164.22 24.64 0 bottom
PR9301  HCB1608KF-121T30  [R0603]  161.6 25 270 top
PR9302  *0_4/S  [S0402]  164.17 23.65 0 bottom
PR9303  1_6  [R0603]  163.64 25.84 0 bottom
PR9304  *1M_4  [R0402]  156.32 23.83 0 bottom
PR9305  *0_4/S  [S0402]  156.8 21.65 180 bottom
PR9306  *10K/F_4  [R0402]  156.42 24.8 0 bottom
PR9307  *2.2_6  [R0603]  159.52 24.57 180 top
PR9308  *0_2/S  [S0201]  163.45 31.09 90 bottom
PR9309  *10K/F_4  [R0402]  157.26 19.69 0 bottom
PR9310  10K/F_4  [R0402]  156.83 20.68 0 bottom
PR9311  150K/F_4  [R0402]  156.12 26.14 90 bottom
PR9312  *0_4/S  [S0402]  164.96 21.52 180 bottom
PR9313  *10K/F_4  [R0402]  163.36 22.66 0 bottom
PR9314  *0_5%_6/S  [S0603]  158.83 29.67 0 top
PR9500  *0_5%_6/S  [S0603]  165.39 35.79 180 top
PR9501  *0_5%_6/S  [S0603]  190.05 27.87 270 top
PR9502  *0_5%_6/S  [S0603]  172.17 34.83 0 top
PR9503  *0_5%_6/S  [S0603]  182.13 30.49 0 top
PR9504  *0_5%_4/S  [S0402]  170.04 29.01 90 top
PR9505  *0_5%_4/S  [S0402]  183.19 35.46 180 top
PR9506  *0_5%_4/S  [S0402]  190.02 34.26 270 top
PR9507  0_5%_4/P  [R0402]  166 29.01 90 top
PR9508  *0_4/P  [R0402]  165.01 29.77 270 top
PR9509  *0_4/S  [S0402]  183.57 34.12 90 top
PR9510  *0_4/S  [S0402]  182.58 34.12 90 top
PR9511  *0_5%_6/S  [S0603]  151.32 34.78 180 top
PR9512  *0_5%_6/S  [S0603]  157.82 34.32 180 top
PR9513  *0_4/S  [S0402]  172.08 30.34 180 top
PR9514  *0_4/S  [S0402]  156.6 28.38 90 top
PR9515  *0_4/S  [S0402]  152.33 28.33 0 top
PR9600  *22_4  [R0402]  180.19 113.89 180 top
PR9601  20K/F_4  [R0402]  138.54 112.45 180 top
PR9602  *100K/F_4  [R0402]  177.71 110.77 270 top
PR9603  *1M_4  [R0402]  177.71 112.68 270 top
PR9604  22_4  [R0402]  176.18 113.72 180 top
PR9605  47K_1%_4  [R0402]  133 112.07 270 top
PR9606  100K/F_4  [R0402]  175.7 110.27 0 top
PR9607  1M_4  [R0402]  173.57 112.27 270 top
PR9608  *0_4/P  [R0402]  111.01 61.19 90 top
PR9609  *0_5%_4/S  [S0402]  109.91 61.19 90 top
PR9610  *0_5%_4/S  [S0402]  114.44 60.03 270 top
PR9611  47K_1%_4  [R0402]  122.82 58.81 180 top
PR9612  *22_4  [R0402]  122.59 60.41 90 top
PR9613  *0_4/P  [R0402]  116.19 58.63 0 top
PR9614  *0_4/P  [R0402]  118.04 58.63 0 top
PR9615  *100K/F_4  [R0402]  115.53 60.05 90 top
PR9616  *1M_4  [R0402]  117 59.72 180 top
PR9617  *0_5%_4  [R0402]  132.8 113.85 270 top
PR9618  *0_5%_4/S  [S0402]  137.65 115.5 180 top
PU8100  AS393MTR-G1  [SOIC8-6-1_27-24AA02]  7.68 113.37 270 bottom
PU8102  74LVC1G07SE-7  [SSOP5-2_1-65-5P-0_9H]  39.99 81.72 180 top
PU8200  BQ24780SRUYR  [QFN28-4X4-4-38P]  127.49 24.57 0 bottom
PU8201  G753T11U  [SOT23-5-2_8-95-5P-G708]  99.55 33.53 180 bottom
PU8600  SY8286BRAC  [QFN20-3X3-45-21P]  178.85 22.56 270 bottom
PU8601  SY8270C  [QFN13-4X3-45]  191.14 22.45 90 bottom
PU8700  RT8231BGQW  [WQFN20-3X3-4-21P]  145.14 16.67 270 bottom
PU8701  RT8097ALGE  [SOT23-6-2_794-9395-6P]  163.94 57.18 0 top
PU8800  MP2969AGQJT-Z  [QFN44-6X5-4-45P]  41.46 100.43 180 top
PU8900  MP8693GDT-Z  [QFN12-3X2-5-13P]  53.63 110.62 180 bottom
PU8901  MP8693GDT-Z  [QFN12-3X2-5-13P]  53.65 118.5 180 bottom
PU9000  MP8693GDT-Z  [QFN12-3X2-5-13P]  53.68 102.26 180 bottom
PU9001  MP8693GDT-Z  [QFN12-3X2-5-13P]  110.45 120.68 270 top
PU9200  APW8713EQBI-TRG  [QFN23-4X4-5-20P]  131.68 125.41 90 bottom
PU9201  G5027ARD1D  [SON8-3X3-65-7P]  139.23 113.7 0 bottom
PU9202  MC74VHC1G08DFT2G  [SOT353-1-2_125-65-5P]  143.37 116.26 0 bottom
PU9300  NB681AGD-Z  [QFN13-2X3-5]  160.03 24.29 180 bottom
PU9500  AOZ1331DI  [SON14-3X2-4-15P-SMT]  187.71 31.27 180 top
PU9501  AOZ1331DI  [SON14-3X2-4-15P-SMT]  168.49 31.93 0 top
PU9502  AOZ1331DI  [SON14-3X2-4-15P-SMT]  154.57 31.37 0 top
PU9600  MC74VHC1GT08DF2G  [SOT353-2_1-65-5P-1_1H]  118.04 116.24 180 top
PU9601  MC74VHC1GT08DF2G  [SOT353-2_1-65-5P-1_1H]  134.88 113.87 90 top
PU9602  MC74VHC1GT08DF2G  [SOT353-2_1-65-5P-1_1H]  112.73 60.2 90 top
Q401  2N7002KDW  [SOT363-2_1-65-6P]  164.35 94.9 180 top
Q402  2N7002KDW  [SOT363-2_1-65-6P]  122.39 109.78 0 bottom
Q403  2N7002K  [SOT23_213-3_3-2]  73.85 70.74 0 top
Q404  PMST3904  [SOT323_213-2_1-1_3-1_1H]  72.65 78.01 90 top
Q406  2N7002K  [SOT23_213-3_3-2]  139.73 60.97 270 top
Q407  BSS84  [SOT23_213-3_3-2]  132.09 60.86 270 top
Q408  BSS84  [SOT23_213-3_3-2]  136.03 61.02 270 top
Q3400  2N7002KTB  [SOT523_213-1_6-1-0_6H]  24.11 123.63 0 top
Q3401  2N7002KTB  [SOT523_213-1_6-1-0_6H]  18.78 115.63 270 top
Q3600  *METR3904-G  [SOT23_213-3_3-2]  215.2 21.54 270 top
Q4000  2N7002KDW  [SOT363-2_1-65-6P]  198.33 59.92 0 top
Q4001  METR3904-G  [SOT23_213-3_3-2]  186.67 73.28 270 top
Q4101  2N7002K  [SOT23_213-3_3-2]  172.73 84.38 180 top
Q4102  2N7002KDW  [SOT363-2_1-65-6P]  165.24 85.64 180 top
Q4103  METR3904-G  [SOT23_213-3_3-2]  168.38 82.86 180 top
Q4104  *2N7002K  [SOT23_213-3_3-2]  175.14 90.96 180 top
Q4105  METR3904-G  [SOT23_213-3_3-2]  169.4 87.08 90 top
Q4109  PJT138K  [SC70-2_1-65-6P]  177.12 87.89 270 top
Q4110  *2N7002K  [SOT23_213-3_3-2]  165.19 88.81 90 top
Q4200  2N7002K  [SOT23_213-3_3-2]  201.91 79.25 270 top
Q4201  2N7002KDW  [SOT363-2_1-65-6P]  207.22 60.2 0 top
Q4202  2N7002KDW  [SOT363-2_1-65-6P]  208.19 62.87 0 top
Q4300  PJE138K  [SOT23_213-3_3-2]  210.75 22.56 0 top
Q4700  2N7002KDW  [SOT363-2_1-65-6P]  188.73 56.24 270 top
Q4701  2N7002K  [SOT23_213-3_3-2]  185.61 55.5 90 top
Q5000  2N7002KTB  [SOT523_213-1_6-1-0_6H]  45.19 53.27 0 top
Q5001  2N7002KTB  [SOT523_213-1_6-1-0_6H]  44.86 51.24 0 top
Q5002  AO3409  [SOT23_213-3_3-2]  138.92 18.14 90 bottom
Q5003  2N7002K  [SOT23_213-3_3-2]  139 21.9 270 bottom
Q5004  2N7002KDW  [SOT363-2_1-65-6P]  44.84 55.5 0 top
Q5005  PJE138K  [SOT23_213-3_3-2]  48.57 54.95 0 top
Q5100  *2N7002KDW  [SOT363-2_1-65-6P]  168.89 66.99 0 top
Q5300  *2N7002KTB  [SOT523_213-1_6-1-0_6H]  71.13 126.42 180 top
Q5301  *2N7002KTB  [SOT523_213-1_6-1-0_6H]  71.13 128.43 180 top
Q5400  2N7002KDW  [SOT363-2_1-65-6P]  49.36 67.26 90 top
Q5401  METR3904-G  [SOT23_213-3_3-2]  171.53 61.27 180 top
Q5402  2N7002KDW  [SOT363-2_1-65-6P]  64.12 26.35 180 top
Q5800  2N7002KDW  [SOT363-2_1-65-6P]  202.47 104.81 180 top
Q6100  *PJA138K  [SOT23_213-3_3-2]  196.63 97.77 270 top
Q6301  PJA138K  [SOT23_213-3_3-2]  226.55 99.5 180 top
Q7500A  *2N7002KTB  [SOT523_213-1_6-1-0_6H]  52.21 56.22 90 top
Q7500B  *2N7002KTB  [SOT523_213-1_6-1-0_6H]  54.62 56.24 90 top
Q7501  2N7002KDW  [SOT363-2_1-65-6P]  47.48 60.38 0 top
Q7502  2N7002K  [SOT23_213-3_3-2]  44.08 60.38 270 top
Q7600  2N7002KDW  [SC70-2_1-65-6P]  13.72 106.56 90 top
Q7601  *2N7002KDW  [SC70-2_1-65-6P]  92.5 134.58 0 bottom
Q7602  *2N7002KDW  [SC70-2_1-65-6P]  92.5 132.45 0 bottom
Q7700  2N7002KDW  [SC70-2_1-65-6P]  26.02 109.02 270 top
Q7701  2N7002KDW  [SC70-2_1-65-6P]  28.3 109.02 90 top
Q7702  2N7002K  [SOT23_213-3_3-2]  57.8 64.61 90 top
R400  49.9/F_4  [R0402]  108.24 109.02 0 bottom
R401  51_4  [R0402]  99.73 109.12 90 bottom
R402  *0_4/S  [S0402]  99.73 107.35 90 bottom
R403  1K_1%_2  [R0201]  97.66 110.32 180 bottom
R404  499/F_4  [R0402]  104.94 108.39 90 bottom
R405  1K_1%_2  [R0201]  123.1 106.66 90 bottom
R411  49.9/F_4  [R0402]  144.76 69.65 90 top
R412  49.9/F_4  [R0402]  128.56 86.97 270 top
R414  10K_5%_2  [R0201]  161.02 101 90 top
R415  200K_4  [R0402]  133.23 69.63 90 top
R416  10K_5%_2  [R0201]  134.32 69.27 270 top
R417  2.2K_2  [R0201]  143.92 93.27 180 bottom
R418  2.2K_2  [R0201]  145.45 93.3 0 bottom
R419  499/F_4  [R0402]  160.61 96.07 0 top
R420  499/F_4  [R0402]  160.66 97.31 0 top
R421  2.2K_2  [R0201]  160.13 94.93 180 top
R422  2.2K_2  [R0201]  161.63 94.65 270 top
R423  10K_5%_2  [R0201]  154.67 87.76 0 top
R424  4.7K/F_4  [R0402]  150.4 92.94 0 top
R425  4.7_5%_4  [R0402]  148.27 72.27 90 bottom
R426  10K_5%_2  [R0201]  150.48 86.01 0 top
R427  4.7_5%_4  [R0402]  143.98 72.24 90 bottom
R428  4.7_5%_4  [R0402]  141.42 73.61 180 bottom
R429  150K/F_4  [R0402]  140.32 71.83 180 bottom
R430  *0_4/S  [S0402]  139.68 74.35 90 bottom
R431  10K_5%_2  [R0201]  150.96 87.38 270 top
R432  *0_4/S  [S0402]  146.16 72.22 90 bottom
R433  4.7_5%_4  [R0402]  147.23 72.24 90 bottom
R436  15_4  [R0402]  162.92 72.47 270 top
R437  15_4  [R0402]  161.55 72.29 0 top
R439  15_4  [R0402]  163.97 72.47 270 top
R441  15_4  [R0402]  162.54 71 180 top
R442  22/F_4  [R0402]  129.42 73.34 90 top
R443  4.7K/F_4  [R0402]  151.75 92.77 90 top
R444  1M_5%_4  [R0402]  136.46 72.04 180 top
R445  *10K_5%_2  [R0201]  150.15 92.08 0 top
R446  100K_4  [R0402]  160.79 70.41 0 top
R447  2.2K_2  [R0201]  166.18 94.98 270 top
R449  *0_4/S  [S0402]  127.36 64.34 180 top
R450  2.2K_2  [R0201]  166.15 95.97 90 top
R451  *470K_4  [R0402]  124.95 72.52 270 top
R452  *0_4/S  [S0402]  126.04 70.87 90 top
R453  10K_5%_2  [R0201]  136.66 71.86 270 bottom
R454  100K_1%_2  [R0201]  135.34 71.76 180 bottom
R455  10K/F_4  [R0402]  128.25 73.21 90 top
R456  4.7K/F_4  [R0402]  131.4 71.73 270 top
R457  *10K_5%_2  [R0201]  113.52 105.47 270 bottom
R458  60.4/F_4  [R0402]  122.26 107.02 90 bottom
R461  1M_5%_4  [R0402]  130.01 74.05 90 bottom
R462  *0_4/S  [S0402]  132.32 74.15 90 top
R463  10K_5%_2  [R0201]  135.19 69.27 270 top
R464  100K_1%_2  [R0201]  127.31 74.68 270 top
R465  1K_1%_2  [R0201]  123.63 107.98 90 bottom
R466  *0_4  [R0402]  127.03 70.86 90 top
R467  20K/F_4  [R0402]  127.39 58.78 270 top
R468  4.7K/F_4  [R0402]  121.24 111.51 0 bottom
R469  *0_4  [R0402]  126.73 62.21 90 top
R470  33/F_4  [R0402]  154.8 89.64 0 top
R471  33/F_4  [R0402]  149.46 89.27 0 top
R472  1K_1%_2  [R0201]  150.27 82.48 0 top
R473  *10K_5%_2  [R0201]  152.21 85.65 180 top
R474  10K_5%_2  [R0201]  147.79 89.26 0 bottom
R476  10K_5%_2  [R0201]  143.19 88.12 0 bottom
R477  100K/F_4  [R0402]  152.43 98.02 0 top
R478  100K/F_4  [R0402]  150.35 97.85 0 top
R479  *10K_5%_2  [R0201]  142.65 94.42 0 bottom
R483  10K_5%_2  [R0201]  137.52 67.89 90 top
R484  10K_5%_2  [R0201]  138.12 68.78 180 top
R485  10K_5%_2  [R0201]  141.99 88.12 0 bottom
R486  8.25K/F_4  [R0402]  142.6 95.38 0 bottom
R487  10K_5%_2  [R0201]  146.92 94.29 0 bottom
R488  2.2K_2  [R0201]  155.05 96.78 270 top
R489  2.2K_2  [R0201]  153.63 96.98 0 top
R490  *100K_1%_2  [R0201]  143.14 70.01 270 top
R491  *100K_1%_2  [R0201]  143.9 70.01 270 top
R492  10K_5%_2  [R0201]  138.49 71.86 270 bottom
R493  10K_5%_2  [R0201]  137.75 71.86 270 bottom
R494  100K_1%_2  [R0201]  136.66 74.33 270 bottom
R495  *100K_1%_2  [R0201]  136.65 72.93 0 top
R496  *100K_1%_2  [R0201]  138.44 72.01 270 top
R497  *20K/F_4  [R0402]  147.43 89.46 270 top
R500  *2.2K_2  [R0201]  153.35 90.63 270 top
R501  10K_5%_2  [R0201]  138.11 69.83 0 top
R504  100K_4  [R0402]  148.42 85.02 0 bottom
R505  *100K_4  [R0402]  149.03 86.64 270 bottom
R506  *100K_4  [R0402]  146.64 85.02 180 bottom
R507  100K_4  [R0402]  144.84 85.02 0 bottom
R508  100K_4  [R0402]  147.43 83.85 180 bottom
R509  *100K_4  [R0402]  145.68 83.83 180 bottom
R510  *100K_4  [R0402]  147.33 86.14 0 bottom
R511  100K_4  [R0402]  147.66 87.2 180 bottom
R512  *100K_4  [R0402]  148.45 90.86 0 bottom
R513  100K_4  [R0402]  146.41 90.86 0 bottom
R514  150/F_4  [R0402]  155.94 77.91 180 top
R515  100K_4  [R0402]  142.48 90.86 180 bottom
R516  *100K_4  [R0402]  144.38 90.86 180 bottom
R517  100K_4  [R0402]  150.73 91.24 180 bottom
R518  *100K_4  [R0402]  148.19 91.93 0 bottom
R519  *100K/F_4  [R0402]  150.53 91.09 0 top
R520  *100K/F_4  [R0402]  148.12 91.22 180 top
R521  *10K_5%_2  [R0201]  151.49 89.59 180 bottom
R522  10K_5%_2  [R0201]  150.35 89.72 90 bottom
R526  2.2K_2  [R0201]  138.03 105.47 90 bottom
R528  2.2K_2  [R0201]  138.79 105.47 90 bottom
R529  *100K/F_4  [R0402]  148.12 92.21 0 top
R531  100K_4  [R0402]  150.48 95.03 180 bottom
R532  10K_5%_2  [R0201]  143.16 89.82 0 bottom
R533  10K_5%_2  [R0201]  146.8 88.25 180 bottom
R534  *10K_5%_2  [R0201]  142.12 89.79 180 bottom
R535  *100K/F_4  [R0402]  152.38 97.8 180 bottom
R536  100K_4  [R0402]  150.44 96.28 180 bottom
R539  100K_4  [R0402]  152.43 96.55 180 bottom
R540  100K_4  [R0402]  154.54 98.48 270 top
R541  *10K_5%_2  [R0201]  146.85 96.09 180 bottom
R542  100K_4  [R0402]  148.36 96.19 180 bottom
R543  24.9/F_4  [R0402]  111.87 106.46 90 bottom
R544  470_4  [R0402]  131.1 69.6 180 top
R545  121/F_4  [R0402]  124.47 74.45 90 top
R546  80.6/F_4  [R0402]  123.43 74.45 90 top
R547  100/F_4  [R0402]  126.04 75.85 0 top
R548  10K/F_4  [R0402]  72.47 72.47 90 top
R549  10K/F_4  [R0402]  73.9 73.16 180 top
R550  *100K/F_4  [R0402]  72.47 69.12 90 top
R551  10K/F_4  [R0402]  74.61 77.55 270 top
R552  100K/F_4  [R0402]  74.61 79.3 270 top
R554  *100K/F_4  [R0402]  148.68 94.11 180 bottom
R555  *10K_5%_2  [R0201]  150.25 94.16 0 bottom
R556  10K_5%_2  [R0201]  156.81 97.06 90 top
R557  10K_5%_2  [R0201]  156.07 97.07 90 top
R558  *10K_5%_2  [R0201]  154.54 99.98 180 top
R559  100K_4  [R0402]  154.18 100.85 180 top
R560  10K_5%_2  [R0201]  156.32 98.35 0 top
R561  *10K_5%_2  [R0201]  156.68 99.07 180 top
R563  *0_4/S  [S0402]  153.53 104.2 180 top
R564  1K_1%_2  [R0201]  143.06 111.21 270 top
R566  113/F_4  [R0402]  142.17 111.08 270 top
R567  100/F_4  [R0402]  144.89 111.82 180 top
R568  10K_5%_2  [R0201]  145.33 96.08 180 bottom
R569  33_1%_2  [R0201]  128.05 74.83 135 bottom
R570  33_1%_2  [R0201]  128.84 73.64 90 bottom
R571  100K/F_4  [R0402]  164.19 82.35 180 top
R572  33_1%_2  [R0201]  127.31 74.5 135 bottom
R574  *100K_1%_2  [R0201]  137.7 74.38 270 bottom
R575  200/F_4  [R0402]  142.88 79.23 0 bottom
R576  75K_1%_4  [R0402]  154.11 77.88 180 top
R577  71.5K_1%_4  [R0402]  157.03 81.06 180 top
R580  10K_5%_2  [R0201]  138.72 58.5 270 top
R583  33_1%_2  [R0201]  140.67 58.45 90 top
R584  1K_1%_2  [R0201]  132.6 58.5 0 top
R585  *0_4P2R_4  [4P2R-0404]  114.77 105.9 0 bottom
R586  10M_4  [R0402]  152.13 83.77 90 top
R587  *2.71K/F_4  [R0402]  142.44 104.77 0 bottom
R588  10K_5%_4  [R0402]  154.16 98.76 0 bottom
R589  33_5%_2  [R0201]  142.25 102.76 0 bottom
R590  33_5%_2  [R0201]  142.25 101.95 0 bottom
R591  200K_1%_4  [R0402]  143.92 101.52 90 bottom
R593  10K_5%_2  [R0201]  155.43 79.94 90 top
R594  10K_5%_2  [R0201]  140.98 69.5 270 top
R595  10K_5%_2  [R0201]  154.03 80.14 0 top
R597  10K_5%_2  [R0201]  154.16 79.05 0 top
R598  *0_4/S  [S0402]  61.91 65.14 180 top
R599  27K/F_4  [R0402]  133.06 73.97 90 bottom
R601  27K/F_4  [R0402]  132.06 73.97 90 bottom
R602  1K_1%_2  [R0201]  59.77 63.22 270 top
R603  49.9/F_4  [R0402]  105.67 106 180 top
R604  1.5K_5%_4  [R0402]  105.29 106.05 270 bottom
R605  1K_1%_2  [R0201]  95.18 105.72 270 bottom
R606  *100K_4  [R0402]  94.32 109.81 180 bottom
R607  *0_6/S  [S0603]  148.7 97.47 180 bottom
R608  *0_6/S  [S0603]  128.68 112.53 90 bottom
R609  100/F_4  [R0402]  113.5 109.56 270 bottom
R610  100/F_4  [R0402]  113.5 107.78 90 bottom
R611  56.2/F_4  [R0402]  107.53 110.42 180 bottom
R612  220/F_4  [R0402]  107.83 107.65 270 bottom
R613  *54.9/F_4  [R0402]  106.87 108.34 90 bottom
R614  100/F_4  [R0402]  105.9 108.34 90 bottom
R615  *0.0002_5%_0805  [R0805]  108.24 92.26 180 top
R616  *0_8/S  [S0805]  103.72 107.07 90 top
R617  *0.0002_5%_0805  [R0805]  108.19 94.42 180 top
R618  *0_8/S  [S0805]  111.87 89.97 0 top
R619  *0_8/S  [S0805]  107.93 107.19 90 top
R620  *0_4/S  [S0402]  123.83 72.19 90 top
R621  *0_4/S  [S0402]  125.94 107.85 270 top
R622  *0_4/S  [S0402]  121.06 107.22 270 bottom
